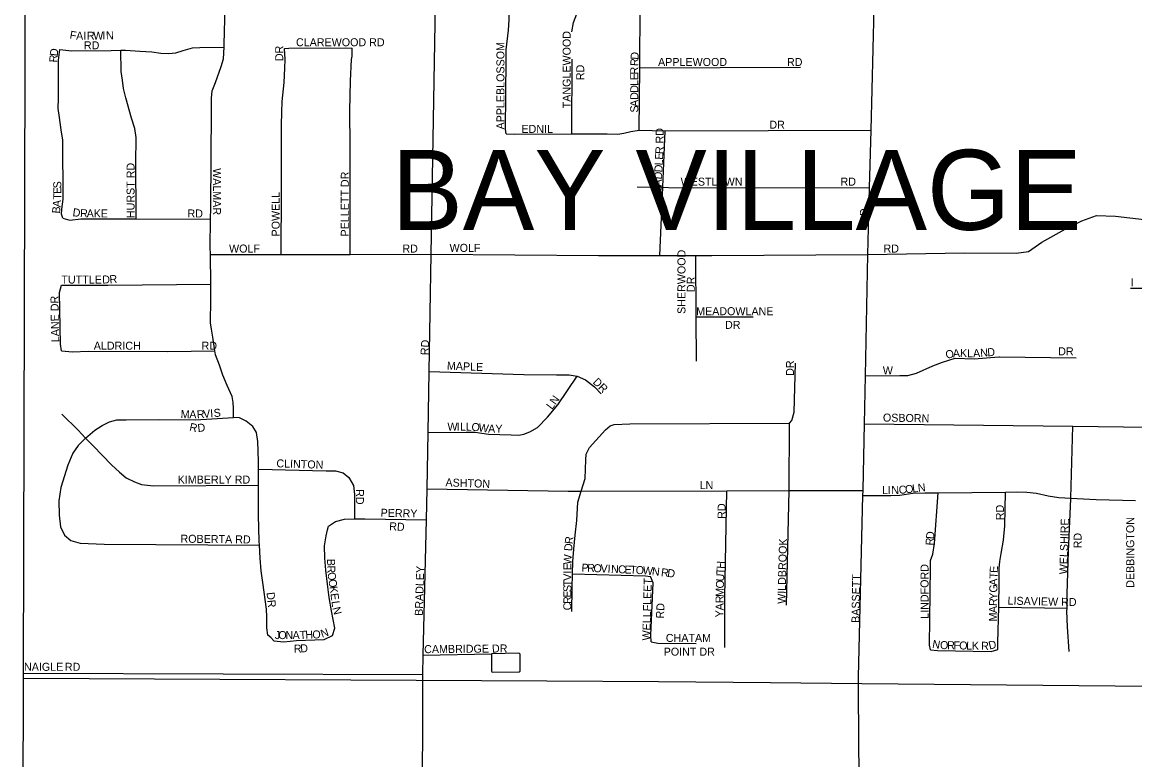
# Model space of a CAD drawing. Extents: x -561 to 1170, y 0 to 846.
# Drawn here: x 38.08 to 56.84, y 265 to 277.44 of the extents above; entities that cross this region are included whole.
import ezdxf

# ---------------------------------------------------------------- set-up
doc = ezdxf.new("R2010")
doc.units = 0
for name, color, linetype in [('GM_X_City_Street', 7, 'Continuous'), ('GM_X_City_Street_Text', 7, 'Continuous'), ('GM_X_Corporation_Text', 7, 'Continuous'), ('GM_X_County', 7, 'Continuous'), ('GM_X_Rail_Line', 7, 'Continuous')]:
    doc.layers.add(name, color=color, linetype=linetype)

msp = doc.modelspace()

# ---------------------------------------------------------------- linework, layer by layer
at = {"layer": 'GM_X_City_Street'}
for points in [[(44.832, 266.279), (44.833, 266.436), (44.841, 266.766), (44.894, 269.05), (44.906, 269.574), (44.922, 270.523), (44.94, 271.551), (44.973, 273.529), (45.065, 278.726), (45.081, 279.658), (45.087, 279.984), (45.108, 280.796), (45.117, 281.619), (45.129, 282.643), (45.156, 284.945), (45.17, 286.202)], [(52.182, 266.15), (52.18, 266.4), (52.256, 269.459), (52.259, 269.546), (52.259, 269.555), (52.28, 270.669), (52.296, 271.478), (52.337, 273.526), (52.366, 274.649), (52.392, 275.624), (52.447, 277.681), (52.449, 277.762), (52.484, 279.056), (52.547, 281.447)], [(46.236, 275.563), (46.226, 275.639), (46.236, 276.808), (46.237, 276.981), (46.276, 277.311), (46.288, 277.484), (46.297, 277.858), (46.308, 278.269), (46.314, 278.383), (46.341, 278.48), (46.396, 278.588), (46.467, 278.788), (46.521, 278.913), (46.541, 278.986), (46.576, 279.118), (46.615, 279.313), (46.644, 279.632), (46.675, 280.52)], [(47.346, 277.28), (47.374, 277.442), (47.456, 277.658), (47.503, 277.76), (47.625, 278.026), (47.713, 278.242), (47.774, 278.491), (47.782, 278.577), (47.847, 279.253), (47.907, 280.515)], [(42.27, 267.062), (42.221, 267.105), (42.205, 267.224), (42.204, 267.413), (42.198, 267.543), (42.137, 267.993), (42.109, 268.188), (42.092, 268.404), (42.079, 268.619), (42.075, 268.691), (42.062, 269.125), (42.063, 269.632), (42.064, 269.902), (42.064, 270.04), (42.052, 270.371), (42.03, 270.522), (41.964, 270.625), (41.856, 270.711), (41.742, 270.77), (41.639, 270.775), (41.638, 270.932), (41.633, 271.029), (41.616, 271.127), (41.534, 271.316), (41.458, 271.489), (41.403, 271.657), (41.337, 271.835), (41.328, 271.899), (41.293, 272.133), (41.271, 272.263), (41.254, 272.371), (41.258, 272.767), (41.256, 273.022), (41.25, 273.525), (41.249, 273.65), (41.255, 274.121), (41.258, 274.311), (41.267, 275.968), (41.272, 276.163), (41.282, 276.288), (41.336, 276.429), (41.432, 276.7), (41.47, 276.825), (41.482, 277.025), (41.485, 277.074), (41.499, 277.703)], [(48.479, 275.624), (48.494, 276.674), (48.495, 276.755), (48.5, 277.654)], [(38.763, 274.137), (38.741, 274.207), (38.746, 274.289), (38.767, 274.457), (38.763, 275.453), (38.736, 275.627), (38.708, 275.838), (38.685, 275.989), (38.69, 276.163), (38.688, 276.802), (38.714, 276.986)], [(38.714, 276.986), (38.915, 276.96), (39.575, 276.968), (39.742, 276.973), (39.818, 276.975), (40.062, 276.954), (40.262, 276.944), (40.414, 276.923), (40.544, 276.919), (40.668, 276.93), (40.793, 276.968), (40.95, 277.012), (41.074, 277.018), (41.482, 277.025)], [(39.997, 274.125), (39.993, 275.15), (39.998, 275.41), (39.997, 275.502), (39.975, 275.654), (39.92, 275.827), (39.827, 276.168), (39.788, 276.325), (39.766, 276.466), (39.744, 276.612), (39.742, 276.973)], [(42.446, 273.526), (42.447, 274.598), (42.45, 275.302), (42.448, 275.708), (42.458, 275.925), (42.463, 276.109), (42.494, 276.429), (42.504, 276.667), (42.509, 276.813), (42.503, 277.003)], [(42.503, 277.003), (42.573, 277.009), (43.537, 277.013), (43.64, 277.008)], [(43.61, 273.528), (43.608, 275.356), (43.6, 275.951), (43.615, 276.455), (43.63, 276.818), (43.64, 276.873), (43.64, 277.008)], [(47.344, 275.56), (47.35, 276.82)], [(48.494, 276.674), (51.203, 276.685)], [(46.236, 275.563), (46.376, 275.557), (47.344, 275.56), (47.944, 275.561), (48.122, 275.555), (48.22, 275.571), (48.339, 275.598), (48.479, 275.624), (48.917, 275.611), (52.392, 275.624)], [(48.832, 273.509), (48.88, 274.66), (48.881, 274.664), (48.917, 275.611)], [(48.448, 274.666), (48.88, 274.66), (48.978, 274.658), (52.366, 274.649)], [(38.763, 274.137), (38.882, 274.105), (39.066, 274.128), (39.997, 274.125), (41.255, 274.121)], [(44.973, 273.529), (47.793, 273.511), (48.832, 273.509), (49.437, 273.508), (49.706, 273.507), (52.337, 273.526), (53.968, 273.555), (54.838, 273.545), (55.048, 273.578), (55.27, 273.735), (55.664, 273.952), (55.945, 274.093), (56.193, 274.185), (56.516, 274.173), (56.998, 274.116)], [(41.25, 273.525), (42.446, 273.526), (43.61, 273.528), (44.973, 273.529)], [(49.451, 271.723), (49.445, 272.475), (49.437, 273.508)], [(38.739, 271.9), (38.722, 272.013), (38.708, 272.886), (38.74, 273.005)], [(38.74, 273.005), (38.908, 273.006), (39.52, 273.008), (41.256, 273.022)], [(56.769, 272.957), (57.249, 272.957), (57.73, 272.928), (58.069, 272.843), (58.409, 272.589), (58.44, 272.568), (58.926, 272.25)], [(49.445, 272.475), (50.406, 272.476)], [(38.739, 271.9), (38.923, 271.884), (39.188, 271.896), (40.525, 271.891), (41.328, 271.899)], [(50.967, 267.608), (51.009, 269.543), (51.014, 270.677), (51.057, 270.725), (51.096, 270.866), (51.116, 271.689)], [(52.296, 271.478), (52.877, 271.481), (53.012, 271.481), (53.158, 271.523), (53.434, 271.647), (53.597, 271.711), (53.808, 271.775), (54.132, 271.763), (54.545, 271.798), (54.551, 271.798)], [(54.551, 271.798), (54.559, 271.799), (55.851, 271.783)], [(44.94, 271.551), (46.536, 271.502), (47.088, 271.494), (47.299, 271.493), (47.434, 271.471), (47.574, 271.411), (47.73, 271.291), (47.838, 271.177)], [(44.922, 270.523), (45.564, 270.526), (45.716, 270.525), (45.943, 270.492), (46.321, 270.48), (46.451, 270.479), (46.537, 270.495), (46.64, 270.532), (46.765, 270.608), (46.933, 270.78), (47.112, 270.991), (47.434, 271.471)], [(38.746, 270.833), (39.019, 270.559), (39.146, 270.427), (39.271, 270.296), (39.582, 269.975), (39.719, 269.852), (39.828, 269.755), (39.969, 269.692), (40.089, 269.644), (40.289, 269.624), (42.063, 269.632)], [(39.146, 270.427), (39.302, 270.564), (39.426, 270.641), (39.55, 270.701), (39.674, 270.734), (39.831, 270.735), (40.383, 270.742), (41.001, 270.734), (41.639, 270.775)], [(47.345, 267.504), (47.352, 267.888), (47.359, 268.137), (47.365, 268.343), (47.377, 268.554), (47.4, 268.792), (47.428, 269.035), (47.445, 269.349), (47.505, 269.534), (47.572, 269.744), (47.584, 270.063), (47.59, 270.155), (47.644, 270.268), (47.911, 270.565), (47.992, 270.635), (48.062, 270.656), (48.322, 270.666), (51.014, 270.677)], [(52.28, 270.669), (55.792, 270.626), (56.651, 270.616), (58.909, 270.601), (60.462, 270.592), (62.256, 270.58), (63.937, 270.57), (64.245, 270.568), (65.472, 270.563), (65.602, 270.562), (65.91, 270.572), (66.686, 270.593), (66.77, 270.595), (68.121, 270.649), (68.473, 270.669), (68.494, 270.669), (68.797, 270.668), (71.721, 270.662)], [(55.731, 266.825), (55.706, 267.242), (55.696, 267.507), (55.697, 267.556), (55.698, 267.799), (55.723, 268.514), (55.759, 269.401), (55.759, 269.413), (55.792, 270.626)], [(39.146, 270.427), (39.021, 270.305), (38.931, 270.174), (38.846, 269.973), (38.731, 269.592), (38.695, 269.37), (38.698, 269.126), (38.721, 268.931), (38.788, 268.791), (38.897, 268.7), (39.054, 268.653), (39.46, 268.635), (42.079, 268.619)], [(42.064, 269.902), (43.205, 269.875), (43.361, 269.875), (43.491, 269.842), (43.588, 269.765), (43.663, 269.63), (43.679, 269.473), (43.682, 269.064)], [(44.906, 269.574), (47.284, 269.534), (47.505, 269.534), (49.96, 269.54), (51.009, 269.543), (52.259, 269.546)], [(49.926, 266.892), (49.925, 267.742), (49.96, 269.54)], [(52.256, 269.459), (52.727, 269.457), (52.878, 269.462), (53.095, 269.499), (53.3, 269.503), (53.522, 269.506), (54.657, 269.517), (54.868, 269.519), (55.019, 269.513), (55.181, 269.496), (55.381, 269.452), (55.559, 269.424), (55.759, 269.413), (56.186, 269.389), (56.851, 269.376)], [(53.396, 266.856), (53.375, 266.932), (53.392, 268.247), (53.392, 268.361), (53.436, 268.469), (53.464, 268.648), (53.522, 269.506)], [(54.531, 266.862), (54.532, 266.981), (54.544, 267.577), (54.553, 268.01), (54.554, 268.226), (54.565, 268.345), (54.587, 268.481), (54.626, 268.708), (54.649, 268.946), (54.657, 269.517)], [(43.311, 267.098), (43.349, 267.222), (43.291, 267.515), (43.254, 267.737), (43.223, 267.964), (43.197, 268.197), (43.182, 268.403), (43.177, 268.609), (43.205, 268.776), (43.227, 268.879), (43.244, 268.944), (43.363, 269.019), (43.514, 269.062), (43.682, 269.064), (43.855, 269.066)], [(43.855, 269.066), (44.894, 269.05)], [(47.359, 268.137), (48.586, 268.105), (48.672, 268.094)], [(48.683, 266.989), (48.679, 267.103), (48.72, 267.985), (48.672, 268.094)], [(54.544, 267.577), (55.697, 267.556)], [(42.27, 267.062), (42.321, 267.005), (42.489, 266.988), (42.705, 267.014), (43.013, 267.023), (43.17, 267.028), (43.311, 267.098)], [(48.683, 266.989), (48.797, 266.967), (49.445, 266.964)], [(44.841, 266.766), (45.991, 266.785)], [(45.991, 266.785), (45.991, 266.497), (45.998, 266.483), (46.007, 266.477), (46.451, 266.481), (46.466, 266.485), (46.473, 266.497), (46.472, 266.781), (46.465, 266.792), (46.453, 266.797), (45.991, 266.785)], [(53.396, 266.856), (53.515, 266.845), (54.418, 266.825), (54.531, 266.862)], [(38.1, 266.459), (44.833, 266.436)], [(44.712, 249.718), (44.743, 251.816), (44.821, 256.718), (44.81, 257.205), (44.832, 266.278), (44.832, 266.279)], [(52.183, 263.466), (52.188, 263.609), (52.193, 264.674), (52.182, 266.129), (52.182, 266.15)]]:
    msp.add_lwpolyline(points, dxfattribs=at)
at = {"layer": 'GM_X_County'}
msp.add_lwpolyline([(38.078, 257.269), (38.1, 266.459), (38.136, 280.768)], dxfattribs=at)
at = {"layer": 'GM_X_Rail_Line'}
msp.add_lwpolyline([(38.104, 266.374), (46.926, 266.33), (48.807, 266.32), (50.698, 266.304), (52.237, 266.285), (56.506, 266.247), (59.789, 266.214), (63.592, 266.177), (68.925, 266.123), (70.922, 266.1), (73.902, 266.071), (82.475, 265.99), (88.766, 265.928)], dxfattribs=at)

# ---------------------------------------------------------------- texts
at = {"layer": 'GM_X_City_Street_Text'}
for s, rotation, p in [('F', 350.0886, (38.87, 277.169)), ('W', 0.9701, (39.276, 277.15)), ('I', 0.9945, (39.431, 277.153)), ('N', 1.3166, (39.491, 277.154)), ('A', 358.4727, (38.985, 277.151)), ('I', 1.0682, (39.11, 277.147)), ('RD', 0, (39.118, 276.987)), ('R', 0.9472, (39.169, 277.149)), ('CLAREWOOD RD', 0, (42.694, 277.039)), ('TANGLEWOOD', 90, (47.326, 275.992)), ('D', 83.0648, (38.674, 276.866)), ('DR', 90, (42.479, 276.788)), ('APPLEBLOSSOM', 90, (46.209, 275.635)), ('D', 86.7195, (48.47, 276.809)), ('R', 85.2948, (38.665, 276.761)), ('R', 88.1904, (48.466, 276.703)), ('APPLEWOOD', 0, (48.8, 276.706)), ('RD', 0, (50.974, 276.706)), ('RD', 90, (47.555, 276.467)), ('R', 89.9757, (48.466, 276.562)), ('E', 89.9863, (48.466, 276.467)), ('L', 89.9863, (48.466, 276.372)), ('D', 89.987, (48.466, 276.253)), ('D', 89.9781, (48.466, 276.134)), ('S', 89.9863, (48.466, 275.92)), ('A', 89.987, (48.466, 276.016)), ('EDNIL', 0, (46.496, 275.577)), ('RD', 90, (48.894, 275.398)), ('DR', 0, (50.677, 275.648)), ('E', 87.0375, (48.882, 275.122)), ('R', 87.0405, (48.887, 275.217)), ('HURST RD', 90, (39.972, 274.139)), ('L', 87.0429, (48.877, 275.027)), ('WALMAR', 270, (41.294, 274.982)), ('PELLETT DR', 90, (43.585, 273.83)), ('D', 87.0372, (48.865, 274.79)), ('D', 87.0431, (48.871, 274.909)), ('S', 89.9956, (38.736, 274.641)), ('S', 89.2487, (48.858, 274.578)), ('A', 87.3766, (48.859, 274.671)), ('WESTLAWN', 0, (49.181, 274.687)), ('RD', 0, (51.877, 274.687)), ('T', 88.3921, (38.734, 274.447)), ('E', 89.9073, (38.736, 274.546)), ('POWELL', 90, (42.419, 273.83)), ('B', 84.6495, (38.713, 274.212)), ('A', 85.0543, (38.723, 274.32)), ('D', 352.4155, (38.921, 274.174)), ('R', 356.9923, (39.05, 274.157)), ('A', 359.6437, (39.164, 274.151)), ('K', 359.9929, (39.283, 274.15)), ('E', 359.9956, (39.402, 274.15)), ('RD', 0, (40.865, 274.15)), ('RD', 90, (52.339, 274.044)), ('WOLF', 0, (41.565, 273.558)), ('RD', 0, (44.488, 273.558)), ('WOLF', 0, (45.284, 273.57)), ('SHERWOOD', 90, (49.262, 272.523)), ('RD', 0, (52.602, 273.558)), ('TUTTLE', 0, (38.738, 273.035)), ('D', 1.4209, (39.428, 273.035)), ('R', 3.9767, (39.553, 273.039)), ('DR', 90, (49.42, 272.891)), ('I', 359.9563, (56.772, 272.988)), ('LANE DR', 90.9561, (38.701, 272.047)), ('MEADOWLANE', 0, (49.442, 272.501)), ('DR', 0, (49.929, 272.271)), ('ALDRICH', 0, (39.284, 271.919)), ('RD', 0, (41.102, 271.919)), ('RD', 86.9884, (44.928, 271.823)), ('O', 13.0503, (53.664, 271.763)), ('A', 3.5211, (53.774, 271.789)), ('K', 358.2074, (53.89, 271.797)), ('L', 358.493, (54.009, 271.793)), ('A', 2.9019, (54.115, 271.79)), ('N', 4.553, (54.238, 271.797)), ('D', 4.5704, (54.357, 271.806)), ('DR', 0, (55.548, 271.824)), ('MAPLE', 357.56, (45.237, 271.584)), ('DR', 90, (51.092, 271.477)), ('W', 0, (52.59, 271.503)), ('DR', 314.9961, (47.689, 271.364)), ('N', 54.8915, (47.072, 270.979)), ('V', 4.916, (41.134, 270.766)), ('I', 4.9016, (41.253, 270.777)), ('S', 4.8964, (41.312, 270.782)), ('L', 52.4197, (47.01, 270.899)), ('M', 357.4127, (40.747, 270.766)), ('A', 359.1539, (40.894, 270.76)), ('R', 4.2099, (41.026, 270.758)), ('OSBORN', 358.9775, (52.591, 270.707)), ('R', 347.2183, (40.888, 270.555)), ('D', 6.5862, (41.041, 270.529)), ('W', 359.9328, (45.248, 270.552)), ('I', 359.9126, (45.403, 270.552)), ('L', 359.939, (45.462, 270.552)), ('L', 359.918, (45.557, 270.552)), ('O', 355.3171, (45.649, 270.552)), ('W', 352.6153, (45.766, 270.543)), ('A', 357.7635, (45.932, 270.522)), ('Y', 359.9929, (46.057, 270.517)), ('CLINTON', 358.1195, (42.362, 269.935)), ('KIMBERLY RD', 0, (40.698, 269.66)), ('ASHTON', 357.9518, (45.213, 269.614)), ('LN', 0, (49.501, 269.566)), ('L', 0.082, (52.578, 269.483)), ('I', 0.0767, (52.673, 269.483)), ('N', 0.5895, (52.734, 269.483)), ('C', 4.7689, (52.864, 269.485)), ('O', 6.443, (52.974, 269.494)), ('L', 6.5093, (53.093, 269.508)), ('N', 7.0353, (53.188, 269.519)), ('RD', 270, (43.705, 269.565)), ('PERRY', 358.7276, (44.12, 269.101)), ('RD', 90, (49.939, 269.066)), ('RD', 90, (54.632, 269.042)), ('WELSHIRE', 88.3643, (55.701, 268.128)), ('DEBBINGTON', 90, (56.83, 267.902)), ('RD', 356.989, (44.263, 268.874)), ('D', 84.4395, (53.451, 268.718)), ('ROBERTA RD', 359.3493, (40.746, 268.663)), ('R', 83.0376, (47.359, 268.633)), ('WILDBROOK', 88.6528, (50.949, 267.629)), ('R', 86.1843, (53.444, 268.612)), ('RD', 90, (55.943, 268.567)), ('D', 85.0875, (47.349, 268.516)), ('B', 270.1822, (43.218, 268.389)), ('W', 86.5768, (47.338, 268.291)), ('E', 89.9727, (47.338, 268.198)), ('P', 357.4582, (47.507, 268.176)), ('R', 357.4867, (47.602, 268.172)), ('O', 357.4639, (47.708, 268.167)), ('V', 357.4933, (47.827, 268.162)), ('I', 357.4639, (47.946, 268.157)), ('N', 357.4708, (48.005, 268.154)), ('C', 357.4804, (48.124, 268.149)), ('H', 87.7915, (49.922, 268.221)), ('LINDFORD', 90, (53.361, 267.379)), ('R', 272.7783, (43.219, 268.275)), ('O', 277.5082, (43.225, 268.156)), ('BRADLEY', 88.2636, (44.832, 267.427)), ('I', 89.9781, (47.338, 268.139)), ('V', 89.9703, (47.338, 268.02)), ('E', 357.4582, (48.231, 268.144)), ('T', 357.4908, (48.326, 268.14)), ('O', 357.4639, (48.421, 268.136)), ('W', 354.798, (48.538, 268.131)), ('N', 353.3847, (48.691, 268.117)), ('R', 353.3554, (48.844, 268.099)), ('D', 353.3732, (48.95, 268.087)), ('U', 87.7973, (49.913, 268.007)), ('T', 87.8005, (49.918, 268.126)), ('BASSETT', 89.0457, (52.196, 267.308)), ('T', 89.097, (54.524, 268.056)), ('E', 86.9111, (54.526, 268.15)), ('O', 277.9126, (43.241, 268.037)), ('K', 277.903, (43.257, 267.92)), ('S', 89.9707, (47.338, 267.83)), ('T', 89.9764, (47.338, 267.925)), ('WELLFLEET', 88.5674, (48.668, 267.011)), ('O', 87.7915, (49.909, 267.888)), ('G', 89.1038, (54.521, 267.819)), ('A', 89.1038, (54.522, 267.937)), ('DR', 276.0111, (42.197, 267.821)), ('E', 277.9079, (43.274, 267.802)), ('E', 89.9764, (47.338, 267.735)), ('R', 89.9703, (47.338, 267.628)), ('R', 89.6478, (49.904, 267.64)), ('M', 88.1418, (49.904, 267.746)), ('Y', 89.1144, (54.519, 267.7)), ('LISAVIEW RD', 358.7277, (54.693, 267.618)), ('L', 277.9079, (43.292, 267.672)), ('N', 284.2324, (43.308, 267.562)), ('C', 89.9757, (47.337, 267.521)), ('RD', 86.9833, (48.897, 267.38)), ('A', 89.9672, (49.904, 267.521)), ('A', 89.1038, (54.515, 267.474)), ('R', 89.1014, (54.517, 267.593)), ('Y', 89.9781, (49.903, 267.403)), ('M', 89.1074, (54.513, 267.332)), ('J', 0.0437, (42.338, 267.036)), ('O', 0.0219, (42.397, 267.036)), ('N', 0.0154, (42.516, 267.036)), ('A', 0.9107, (42.637, 267.036)), ('T', 2.1403, (42.759, 267.038)), ('H', 2.0552, (42.854, 267.042)), ('O', 1.3772, (42.972, 267.046)), ('N', 19.4532, (43.136, 267.057)), ('CHATAM', 0, (48.931, 266.988)), ('N', 350.3149, (53.417, 266.892)), ('O', 357.7466, (53.553, 266.87)), ('R', 359.0678, (53.675, 266.866)), ('F', 359.0777, (53.782, 266.864)), ('O', 359.0382, (53.877, 266.862)), ('L', 359.0665, (53.996, 266.86)), ('K', 359.0694, (54.091, 266.859)), ('R', 359.0528, (54.246, 266.856)), ('D', 14.0043, (54.391, 266.859)), ('R', 1.8703, (42.66, 266.806)), ('D', 3.271, (42.77, 266.81)), ('CAMBRIDGE DR', 0.5402, (44.856, 266.798)), ('POINT DR', 0, (48.895, 266.756)), ('NAIGLE', 0, (38.108, 266.501)), ('RD', 0, (38.797, 266.501))]:
    msp.add_text(s, height=0.135, rotation=rotation, dxfattribs=at).set_placement(p)
at = {"layer": 'GM_X_Corporation_Text'}
msp.add_text('BAY VILLAGE', height=1.35, rotation=0, dxfattribs=at).set_placement((44.304, 273.941))

doc.saveas('drawing.dxf')
